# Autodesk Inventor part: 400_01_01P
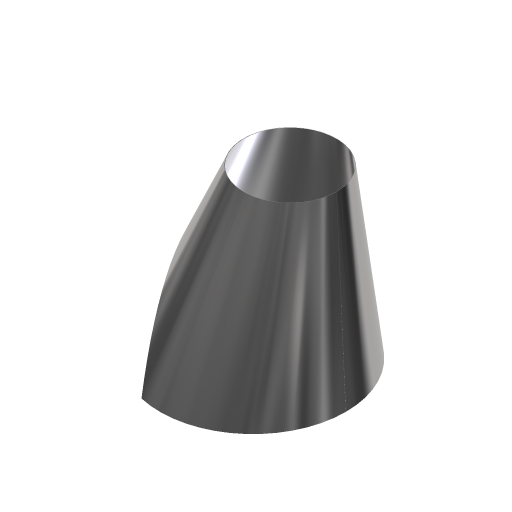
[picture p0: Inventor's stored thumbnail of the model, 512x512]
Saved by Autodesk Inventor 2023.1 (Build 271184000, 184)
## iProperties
Company: Fabian Stasiak CAD Consulting
Category: Autodesk® Inventor® Tutorial Series
Created: 2017-01
Part Number: 400_01_01P
Material: Steel
Document SubType Name: Konstrukcja blachowa
Designer: F.Stasiak
Density: 7.85 g/cm^3
Sheet Metal Rule: Blacha stalowa 1.0 mm/Spoina liniowa
Sheet Metal Width: 0,000 mm
Sheet Metal Length: 0,000 mm
Sheet Metal Area: 0,000 mm^2
Appearance: Semi-Polished
Description: Cone 125x250
Mass: 3686.66 g
Surface Area: 9428.07 cm^2
Volume: 469.638 cm^3
Catalog Web Link: www.expertbooks.eu
FLATAREA: =<FLAT PATTERN AREA>
Thickness: 1,000 mm
Author: F.Stasiak
Subject: Sheet Metal Design. Basic and Advanced techniques
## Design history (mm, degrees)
derived "400_01_Portki_BAZA.ipt"
feature "Pogrubienie1" dims "d1" = 1 (= Thickness), "d2" = 1 (= Thickness)
node "Punkt konstrukcyjny3"
node "Punkt konstrukcyjny4"
feature "Rozdarcie1" dims "d3" = 1 (= GapSize)
node "Bryła1"
body "Srf1"
feature "Srf2::Pochodne"
other parameters: "Thickness" = 1 (derived), "WspółczynnikK" = 4.4, "BendRadius" = 1 (= Thickness), "BendReliefWidth" = 1 (= Thickness), "BendReliefDepth" = 0.5 (= 0.5 x Thickness), "CornerReliefSize" = 4 (= 4 x Thickness), "OdstępPołączenia" = 0.01, "MinimumRemnant" = 2 (= 2 x Thickness), "TransitionRadius" = 1 (= BendRadius), "JacobiRadiusSize" = 1 (= BendRadius), "GapSize" = 1 (= Thickness), "d4" = 1 (= Thickness)
